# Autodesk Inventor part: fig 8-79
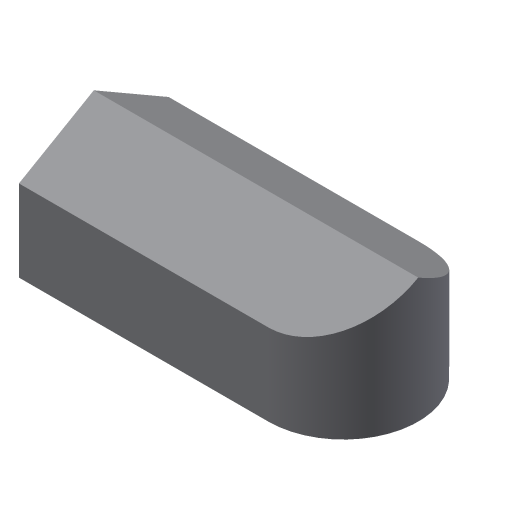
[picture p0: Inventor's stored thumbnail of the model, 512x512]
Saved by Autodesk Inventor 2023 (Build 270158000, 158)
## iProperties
Created: 2011-07
Part Number: fig 8-79
Material: Generic
Document SubType Name: Modeling
Designer: CadCim
Density: 1 g/cm^3
Appearance: Default
Author: CadCim
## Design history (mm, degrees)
sketch "Sketch1"
  geometry: L1 (-16, 5)-(-16, -7); L2 (-16, -7)-(4, -7); L3 (4, 5)-(-16, 5); A1 r 6 centre (4, -1) between (4, -7) and (4, 5); 1 further point
  constraints: 6 end point, 2 point on circle, 2 tangent, 1 centre point, 1 parallel, 1 perpendicular, 1 vertical
extrude "Extrusion1" new body sketch "Sketch1" distance "d0" = 10; taper "d1" = 0 deg
sketch "Sketch2"
  geometry: L1 (-16, -1)-(10, -1); 1 further point
  constraints: 2 end point, 1 horizontal
feature "FaceDraft1" sketch "Sketch2" dims angle "d2" = 30 deg
body "Solid1"
